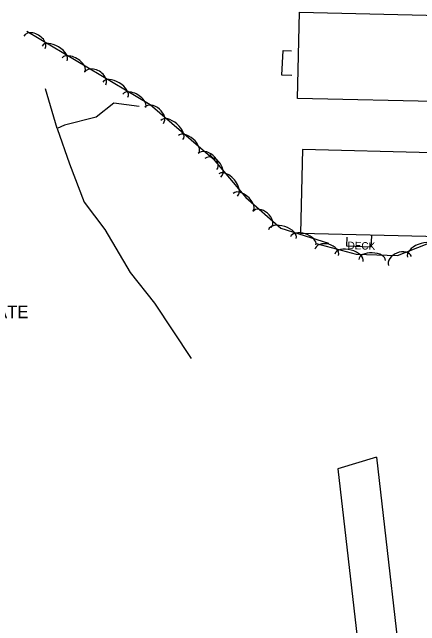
# Model space of a CAD drawing. Extents: x 978516 to 993312, y 1836504 to 1846212.
# Drawn here: x 991462.3 to 991626, y 1839704.5 to 1839951.3 of the extents above; entities that cross this region are included whole.
import ezdxf

# ---------------------------------------------------------------- set-up
doc = ezdxf.new("R2010")
doc.units = 0
for name, color, linetype in [('R_Proposed Road', 7, 'Continuous'), ('S_BUILDING', 7, 'Continuous'), ('S_MISC_STRUCTURES', 7, 'Continuous'), ('S_MISC_STRUCTURES_ANNOT', 7, 'Continuous'), ('S_SIDE_DRAIN_ANNOT', 7, 'Continuous'), ('S_SIDEWALK', 7, 'Continuous'), ('S_STREAM', 7, 'Continuous'), ('S_TREE', 7, 'Continuous')]:
    doc.layers.add(name, color=color, linetype=linetype)

msp = doc.modelspace()

# ---------------------------------------------------------------- linework, layer by layer
at = {"layer": 'R_Proposed Road'}
msp.add_line((991608.69, 1839772.31), (991593.13, 1839767.59), dxfattribs=at)
for points in [[(991608.69, 1839772.31), (991620.9, 1839665.56)], [(991593.13, 1839767.59), (991605, 1839663.75)]]:
    msp.add_lwpolyline(points, dxfattribs=at)
at = {"layer": 'S_BUILDING'}
for points in [[(991577.74, 1839951.34), (991634.28, 1839950.06), (991633.87, 1839931.57), (991637.95, 1839931.48), (991637.58, 1839915.25), (991576.95, 1839916.61)], [(991578.06, 1839862.51), (991634.05, 1839861.15), (991634.57, 1839882.56), (991630.71, 1839882.65), (991631, 1839894.8), (991578.88, 1839896.08)]]:
    msp.add_lwpolyline(points, close=True, dxfattribs=at)
at = {"layer": 'S_MISC_STRUCTURES'}
msp.add_lwpolyline([(991596.72, 1839860.82), (991596.62, 1839857.31), (991606.55, 1839856.97), (991606.7, 1839861.41)], dxfattribs=at)
at = {"layer": 'S_SIDEWALK'}
msp.add_lwpolyline([(991574.66, 1839925.86), (991570.65, 1839926), (991571.13, 1839935.96), (991574.45, 1839935.85)], dxfattribs=at)
at = {"layer": 'S_STREAM'}
for points in [[(991480.3, 1839904.61), (991475.6, 1839920.6)], [(991513.28, 1839913.39), (991503.09, 1839914.82), (991495.92, 1839909.16), (991483.3, 1839905.96), (991480.3, 1839904.61), (991485.22, 1839890.37), (991491.17, 1839874.91)], [(991491.17, 1839874.91), (991499.46, 1839863.94), (991509.63, 1839846.7), (991519.41, 1839834.32), (991534.19, 1839812.06)]]:
    msp.add_lwpolyline(points, dxfattribs=at)
at = {"layer": 'S_TREE'}
for points in [[(991468.08, 1839943.79), (991517.71, 1839914.27), (991542.92, 1839892.46)], [(991541.51, 1839894.05), (991556.13, 1839876.76), (991570.17, 1839864.5), (991589.33, 1839858.38)], [(991584.41, 1839858.28), (991600.43, 1839854.02), (991617.06, 1839853.45), (991629.06, 1839858.22), (991640.11, 1839863.75), (991653.4, 1839861.52), (991663.86, 1839852.15), (991675.14, 1839839.75), (991685.86, 1839829.88), (991687.33, 1839811.83), (991685.13, 1839794.49), (991690.95, 1839777.53), (991705.38, 1839765.26)]]:
    msp.add_lwpolyline(points, dxfattribs=at)
for centre, major_axis, ratio, start_param, end_param in [((991471.17, 1839939.26), (-4.24, 2.56), 0.668061, 3.153197, 6.29479), ((991479.25, 1839934.75), (-5.03, 3.02), 0.536254, 3.148832, 6.290424), ((991486.86, 1839930.22), (-4.58, 2.75), 0.52711, 3.148612, 6.290205), ((991495.58, 1839924.73), (-4.24, 2.56), 0.668061, 3.153197, 6.29479), ((991503.66, 1839920.22), (-5.03, 3.02), 0.536254, 3.148832, 6.290424), ((991511.28, 1839915.69), (-4.58, 2.75), 0.52711, 3.148612, 6.290205), ((991519.24, 1839909.88), (-3.75, 3.24), 0.666966, 3.141593, 6.283185), ((991526.4, 1839904.02), (-4.44, 3.84), 0.535355, 3.141593, 6.283185), ((991533.11, 1839898.22), (-4.04, 3.5), 0.526226, 3.141593, 6.283185), ((991540.74, 1839891.28), (-3.75, 3.24), 0.666966, 3.141593, 6.283185), ((991542.89, 1839888.76), (-3.21, 3.76), 0.683582, 3.133396, 6.274989), ((991549.05, 1839881.87), (-3.79, 4.46), 0.548703, 3.136578, 6.278171), ((991555.04, 1839874.91), (-4.02, 3.52), 0.538563, 3.144885, 6.286478), ((991562.63, 1839867.94), (-3.72, 3.27), 0.682597, 3.14714, 6.288732), ((991570.77, 1839862.09), (-5.59, 1.79), 0.547925, 3.143936, 6.285528), ((991579.21, 1839859.39), (-5.09, 1.63), 0.538582, 3.143863, 6.285455), ((991588.58, 1839854.7), (-4.79, 1.27), 0.685307, 3.141593, 6.283185), ((991626.6, 1839854.96), (-5.45, -2.17), 0.550077, 3.141593, 6.283185), ((991597.6, 1839852.57), (-5.67, 1.51), 0.550077, 3.141593, 6.283185), ((991606.86, 1839851.68), (-5.34, 0.18), 0.540696, 3.141593, 6.283185), ((991618.09, 1839851.3), (-4.6, -1.83), 0.685307, 3.141593, 6.283185)]:
    msp.add_ellipse(centre, major_axis=major_axis, ratio=ratio, start_param=start_param, end_param=end_param, dxfattribs=at)

# ---------------------------------------------------------------- texts
at = {"layer": 'S_MISC_STRUCTURES_ANNOT'}
msp.add_text('DECK', height=3, rotation=358.0701, dxfattribs=at).set_placement((991596.94, 1839856.1))
at = {"layer": 'S_SIDE_DRAIN_ANNOT'}
msp.add_text('CN:100 CANT LOCATE', height=5, dxfattribs=at).set_placement((991397.41, 1839828.26))

doc.saveas('drawing.dxf')
